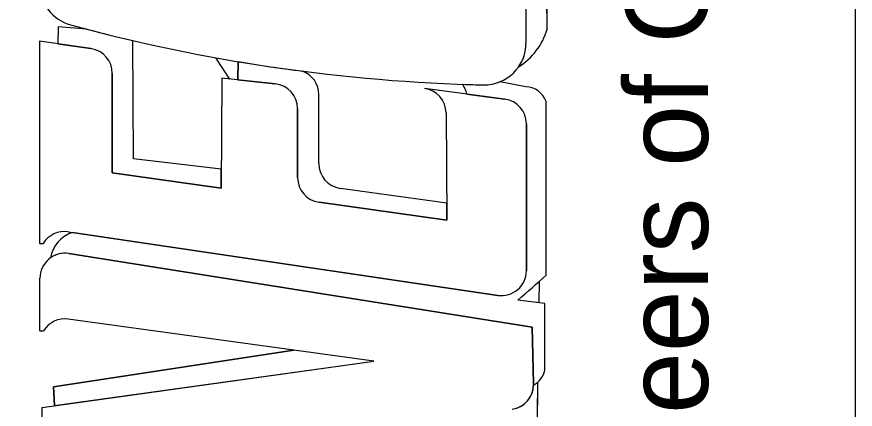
# Model space of a CAD drawing. Extents: x 1485751 to 1485785, y 230696.6 to 230718.6.
# Drawn here: x 1485783.769 to 1485784.533, y 230715.175 to 230715.532 of the extents above; entities that cross this region are included whole.
import ezdxf

# ---------------------------------------------------------------- set-up
doc = ezdxf.new("R2010")
doc.units = 0
doc.layers.add('SH_Border', color=7, linetype='Continuous')

msp = doc.modelspace()

# ---------------------------------------------------------------- linework, layer by layer
at = {"layer": 'SH_Border'}
for p, q in [((1485784.25235, 230715.52061), (1485784.25132, 230715.64075)), ((1485784.25235, 230715.52061), (1485784.25132, 230715.64075)), ((1485784.25235, 230715.52061), (1485784.25132, 230715.64075)), ((1485784.23301, 230715.61233), (1485784.23301, 230715.5077)), ((1485784.23301, 230715.61233), (1485784.23301, 230715.5077)), ((1485784.23301, 230715.61233), (1485784.23301, 230715.5077)), ((1485783.80699, 230715.52266), (1485783.80683, 230715.50714)), ((1485783.80699, 230715.52266), (1485783.80683, 230715.50714)), ((1485783.80699, 230715.52266), (1485783.80683, 230715.50714)), ((1485783.83291, 230715.52058), (1485783.80699, 230715.52266)), ((1485783.83291, 230715.52058), (1485783.80699, 230715.52266)), ((1485783.83291, 230715.52058), (1485783.80699, 230715.52266)), ((1485783.83689, 230715.50284), (1485783.79009, 230715.50953)), ((1485783.79009, 230715.50953), (1485783.79009, 230715.32551)), ((1485783.83689, 230715.50284), (1485783.79009, 230715.50953)), ((1485783.79009, 230715.50953), (1485783.79009, 230715.32551)), ((1485783.83689, 230715.50284), (1485783.79009, 230715.50953)), ((1485783.79009, 230715.50953), (1485783.79009, 230715.32551)), ((1485783.87574, 230715.40252), (1485783.87515, 230715.51016)), ((1485783.87574, 230715.40252), (1485783.87515, 230715.51016)), ((1485783.87574, 230715.40252), (1485783.87515, 230715.51016)), ((1485783.96336, 230715.47519), (1485783.95069, 230715.49456)), ((1485783.96336, 230715.47519), (1485783.95069, 230715.49456)), ((1485783.96336, 230715.47519), (1485783.95069, 230715.49456)), ((1485783.97073, 230715.47442), (1485783.97099, 230715.49103)), ((1485783.97073, 230715.47442), (1485783.97099, 230715.49103)), ((1485783.97073, 230715.47442), (1485783.97099, 230715.49103)), ((1485783.85637, 230715.38981), (1485783.85637, 230715.48038)), ((1485783.85637, 230715.38981), (1485783.85637, 230715.48038)), ((1485783.85637, 230715.38981), (1485783.85637, 230715.48038)), ((1485783.95622, 230715.47594), (1485783.95536, 230715.37602)), ((1485783.95622, 230715.47594), (1485783.95536, 230715.37602)), ((1485783.95622, 230715.47594), (1485783.95536, 230715.37602)), ((1485784.00475, 230715.47087), (1485783.95622, 230715.47594)), ((1485784.00475, 230715.47087), (1485783.95622, 230715.47594)), ((1485784.00475, 230715.47087), (1485783.95622, 230715.47594)), ((1485784.23285, 230715.46824), (1485784.20934, 230715.47262)), ((1485784.23285, 230715.46824), (1485784.20934, 230715.47262)), ((1485784.23285, 230715.46824), (1485784.20934, 230715.47262)), ((1485784.2137, 230715.45692), (1485784.14059, 230715.46667)), ((1485784.2137, 230715.45692), (1485784.14059, 230715.46667)), ((1485784.2137, 230715.45692), (1485784.14059, 230715.46667)), ((1485784.04446, 230715.39822), (1485784.04446, 230715.46102)), ((1485784.04446, 230715.39822), (1485784.04446, 230715.46102)), ((1485784.04446, 230715.39822), (1485784.04446, 230715.46102)), ((1485784.25132, 230715.29676), (1485784.25132, 230715.45489)), ((1485784.25132, 230715.29676), (1485784.25132, 230715.45489)), ((1485784.25132, 230715.29676), (1485784.25132, 230715.45489)), ((1485784.02508, 230715.38551), (1485784.02508, 230715.4483)), ((1485784.02508, 230715.38551), (1485784.02508, 230715.4483)), ((1485784.02508, 230715.38551), (1485784.02508, 230715.4483)), ((1485784.16028, 230715.44437), (1485784.16109, 230715.34674)), ((1485784.16028, 230715.44437), (1485784.16109, 230715.34674)), ((1485784.16028, 230715.44437), (1485784.16109, 230715.34674)), ((1485784.23339, 230715.30084), (1485784.23339, 230715.43443)), ((1485784.23339, 230715.30084), (1485784.23339, 230715.43443)), ((1485784.23339, 230715.30084), (1485784.23339, 230715.43443)), ((1485783.95551, 230715.39327), (1485783.87574, 230715.40252)), ((1485783.95551, 230715.39327), (1485783.87574, 230715.40252)), ((1485783.95551, 230715.39327), (1485783.87574, 230715.40252)), ((1485783.95536, 230715.37602), (1485783.85637, 230715.38981)), ((1485783.95536, 230715.37602), (1485783.85637, 230715.38981)), ((1485783.95536, 230715.37602), (1485783.85637, 230715.38981)), ((1485784.16096, 230715.36218), (1485784.064, 230715.37575)), ((1485784.16096, 230715.36218), (1485784.064, 230715.37575)), ((1485784.16096, 230715.36218), (1485784.064, 230715.37575)), ((1485784.16109, 230715.34674), (1485784.04463, 230715.36304)), ((1485784.16109, 230715.34674), (1485784.04463, 230715.36304)), ((1485784.16109, 230715.34674), (1485784.04463, 230715.36304)), ((1485783.81609, 230715.33622), (1485784.20739, 230715.2784)), ((1485783.81609, 230715.33622), (1485784.20739, 230715.2784)), ((1485783.81609, 230715.33622), (1485784.20739, 230715.2784)), ((1485783.79009, 230715.32551), (1485783.79336, 230715.32551)), ((1485783.79009, 230715.32551), (1485783.79336, 230715.32551)), ((1485783.79009, 230715.32551), (1485783.79336, 230715.32551)), ((1485784.23859, 230715.24939), (1485783.81676, 230715.31644)), ((1485784.23859, 230715.24939), (1485783.81676, 230715.31644)), ((1485784.23859, 230715.24939), (1485783.81676, 230715.31644)), ((1485783.79051, 230715.2461), (1485783.79051, 230715.29404)), ((1485783.79051, 230715.2461), (1485783.79051, 230715.29404)), ((1485783.79051, 230715.2461), (1485783.79051, 230715.29404)), ((1485784.2451, 230715.27174), (1485784.24545, 230715.29141)), ((1485784.2451, 230715.27174), (1485784.24545, 230715.29141)), ((1485784.2451, 230715.27174), (1485784.24545, 230715.29141)), ((1485784.2503, 230715.27109), (1485784.22567, 230715.27417)), ((1485784.2503, 230715.27109), (1485784.22567, 230715.27417)), ((1485784.2503, 230715.27109), (1485784.22567, 230715.27417)), ((1485784.2503, 230715.2105), (1485784.2503, 230715.27109)), ((1485784.2503, 230715.2105), (1485784.2503, 230715.27109)), ((1485784.2503, 230715.2105), (1485784.2503, 230715.27109)), ((1485784.09452, 230715.21839), (1485783.8163, 230715.25684)), ((1485784.09452, 230715.21839), (1485783.8163, 230715.25684)), ((1485784.09452, 230715.21839), (1485783.8163, 230715.25684)), ((1485783.79051, 230715.2461), (1485783.79378, 230715.2461)), ((1485783.79051, 230715.2461), (1485783.79378, 230715.2461)), ((1485783.79051, 230715.2461), (1485783.79378, 230715.2461)), ((1485784.23995, 230715.19789), (1485784.23859, 230715.24939)), ((1485784.23995, 230715.19789), (1485784.23859, 230715.24939)), ((1485784.23995, 230715.19789), (1485784.23859, 230715.24939)), ((1485783.80289, 230715.1951), (1485784.02153, 230715.22848)), ((1485783.80289, 230715.1951), (1485784.02153, 230715.22848)), ((1485783.80289, 230715.1951), (1485784.02153, 230715.22848)), ((1485783.79244, 230715.17654), (1485784.09452, 230715.21839)), ((1485783.79244, 230715.17654), (1485784.09452, 230715.21839)), ((1485783.79244, 230715.17654), (1485784.09452, 230715.21839)), ((1485784.24304, 230715.11402), (1485784.24376, 230715.19938)), ((1485784.24304, 230715.11402), (1485784.24376, 230715.19938)), ((1485784.24304, 230715.11402), (1485784.24376, 230715.19938)), ((1485783.80385, 230715.17812), (1485783.80289, 230715.1951)), ((1485783.80385, 230715.17812), (1485783.80289, 230715.1951)), ((1485783.80385, 230715.17812), (1485783.80289, 230715.1951)), ((1485783.79244, 230715.11608), (1485783.79244, 230715.17654)), ((1485783.79244, 230715.11608), (1485783.79244, 230715.17654)), ((1485783.79244, 230715.11608), (1485783.79244, 230715.17654))]:
    msp.add_line(p, q, dxfattribs=at)
msp.add_lwpolyline([(1485753.03285, 230718.14083), (1485784.53285, 230718.14083), (1485784.53285, 230697.14083), (1485753.03285, 230697.14083)], close=True, dxfattribs=at)
for points in [[(1485784.25235, 230715.52061), (1485784.25132, 230715.64075)], [(1485784.25235, 230715.52061), (1485784.25132, 230715.64075)], [(1485784.25235, 230715.52061), (1485784.25132, 230715.64075)], [(1485784.23301, 230715.61233), (1485784.23301, 230715.5077)], [(1485784.23301, 230715.61233), (1485784.23301, 230715.5077)], [(1485784.23301, 230715.61233), (1485784.23301, 230715.5077)], [(1485783.83291, 230715.52058), (1485783.80699, 230715.52266), (1485783.80683, 230715.50714), (1485783.83689, 230715.50284)], [(1485783.83291, 230715.52058), (1485783.80699, 230715.52266), (1485783.80683, 230715.50714), (1485783.83689, 230715.50284)], [(1485783.83291, 230715.52058), (1485783.80699, 230715.52266), (1485783.80683, 230715.50714), (1485783.83689, 230715.50284)], [(1485783.85637, 230715.48038), (1485783.85637, 230715.38981), (1485783.95536, 230715.37602), (1485783.95551, 230715.39327), (1485783.87574, 230715.40252), (1485783.87515, 230715.51016)], [(1485783.85637, 230715.48038), (1485783.85637, 230715.38981), (1485783.95536, 230715.37602), (1485783.95551, 230715.39327), (1485783.87574, 230715.40252), (1485783.87515, 230715.51016)], [(1485783.85637, 230715.48038), (1485783.85637, 230715.38981), (1485783.95536, 230715.37602), (1485783.95551, 230715.39327), (1485783.87574, 230715.40252), (1485783.87515, 230715.51016)], [(1485783.97099, 230715.49103), (1485783.97073, 230715.47442), (1485784.00475, 230715.47087)], [(1485783.97099, 230715.49103), (1485783.97073, 230715.47442), (1485784.00475, 230715.47087)], [(1485783.97099, 230715.49103), (1485783.97073, 230715.47442), (1485784.00475, 230715.47087)], [(1485784.23285, 230715.46824), (1485784.20934, 230715.47262)], [(1485784.23285, 230715.46824), (1485784.20934, 230715.47262)], [(1485784.23285, 230715.46824), (1485784.20934, 230715.47262)], [(1485784.04446, 230715.39822), (1485784.04446, 230715.46102)], [(1485784.04446, 230715.39822), (1485784.04446, 230715.46102)], [(1485784.04446, 230715.39822), (1485784.04446, 230715.46102)], [(1485784.17918, 230715.46152), (1485784.2137, 230715.45692)], [(1485784.17918, 230715.46152), (1485784.2137, 230715.45692)], [(1485784.17918, 230715.46152), (1485784.2137, 230715.45692)], [(1485784.25132, 230715.29676), (1485784.25132, 230715.45489)], [(1485784.25132, 230715.29676), (1485784.25132, 230715.45489)], [(1485784.25132, 230715.29676), (1485784.25132, 230715.45489)], [(1485784.02508, 230715.4483), (1485784.02508, 230715.38551)], [(1485784.02508, 230715.4483), (1485784.02508, 230715.38551)], [(1485784.02508, 230715.4483), (1485784.02508, 230715.38551)], [(1485784.23339, 230715.43443), (1485784.23339, 230715.30084)], [(1485784.23339, 230715.43443), (1485784.23339, 230715.30084)], [(1485784.23339, 230715.43443), (1485784.23339, 230715.30084)], [(1485784.04463, 230715.36304), (1485784.16109, 230715.34674), (1485784.16096, 230715.36218), (1485784.064, 230715.37575)], [(1485784.04463, 230715.36304), (1485784.16109, 230715.34674), (1485784.16096, 230715.36218), (1485784.064, 230715.37575)], [(1485784.04463, 230715.36304), (1485784.16109, 230715.34674), (1485784.16096, 230715.36218), (1485784.064, 230715.37575)], [(1485784.20739, 230715.2784), (1485783.81978, 230715.33567)], [(1485784.20739, 230715.2784), (1485783.81978, 230715.33567)], [(1485784.20739, 230715.2784), (1485783.81978, 230715.33567)], [(1485783.81676, 230715.31644), (1485784.23859, 230715.24939), (1485784.23995, 230715.19789)], [(1485783.81676, 230715.31644), (1485784.23859, 230715.24939), (1485784.23995, 230715.19789)], [(1485783.81676, 230715.31644), (1485784.23859, 230715.24939), (1485784.23995, 230715.19789)], [(1485784.2503, 230715.2105), (1485784.2503, 230715.27109), (1485784.2451, 230715.27174), (1485784.22567, 230715.27417)], [(1485784.2503, 230715.2105), (1485784.2503, 230715.27109), (1485784.2451, 230715.27174), (1485784.22567, 230715.27417)], [(1485784.2503, 230715.2105), (1485784.2503, 230715.27109), (1485784.2451, 230715.27174), (1485784.22567, 230715.27417)], [(1485783.80385, 230715.17812), (1485784.09452, 230715.21839), (1485784.02153, 230715.22848), (1485783.80289, 230715.1951), (1485783.80385, 230715.17812)], [(1485783.80385, 230715.17812), (1485784.09452, 230715.21839), (1485784.02153, 230715.22848), (1485783.80289, 230715.1951), (1485783.80385, 230715.17812)], [(1485783.80385, 230715.17812), (1485784.09452, 230715.21839), (1485784.02153, 230715.22848), (1485783.80289, 230715.1951), (1485783.80385, 230715.17812)], [(1485784.15842, 230715.16607), (1485784.18677, 230715.12362), (1485784.24304, 230715.11402), (1485784.24376, 230715.19938)], [(1485784.15842, 230715.16607), (1485784.18677, 230715.12362), (1485784.24304, 230715.11402), (1485784.24376, 230715.19938)], [(1485784.15842, 230715.16607), (1485784.18677, 230715.12362), (1485784.24304, 230715.11402), (1485784.24376, 230715.19938)]]:
    msp.add_lwpolyline(points, dxfattribs=at)
for centre, radius, start, end in [((1485783.82829, 230715.56095), 0.03781, 180, 254.79162), ((1485783.82829, 230715.56095), 0.03781, 180, 254.79162), ((1485783.82829, 230715.56095), 0.03781, 180, 254.79162), ((1485784.23016, 230717.0392), 1.56971, 254.79162, 268.69253), ((1485784.23016, 230717.0392), 1.56971, 254.79162, 268.69253), ((1485784.23016, 230717.0392), 1.56971, 254.79162, 268.69253), ((1485784.23016, 230717.0392), 1.56971, 255.34062, 256.92894), ((1485784.23016, 230717.0392), 1.56971, 255.34062, 256.92894), ((1485784.23016, 230717.0392), 1.56971, 255.34062, 256.92894), ((1485784.19322, 230715.53826), 0.06171, 302.39655, 343.37547), ((1485784.19322, 230715.53826), 0.06171, 302.39655, 343.37547), ((1485784.19322, 230715.53826), 0.06171, 302.39655, 343.37547), ((1485784.19322, 230715.53826), 0.06171, 302.39655, 343.37547), ((1485784.19322, 230715.53826), 0.06171, 302.39655, 343.37547), ((1485784.19322, 230715.53826), 0.06171, 302.39655, 343.37547), ((1485784.1952, 230715.5077), 0.03781, 268.69253, 0), ((1485784.1952, 230715.5077), 0.03781, 268.69253, 0), ((1485784.1952, 230715.5077), 0.03781, 268.69253, 0), ((1485784.1952, 230715.5077), 0.03781, 325.27661, 0), ((1485784.1952, 230715.5077), 0.03781, 325.27661, 0), ((1485784.1952, 230715.5077), 0.03781, 325.27661, 0), ((1485783.83368, 230715.48038), 0.02269, 0, 81.86464), ((1485783.83368, 230715.48038), 0.02269, 0, 81.86464), ((1485783.83368, 230715.48038), 0.02269, 0, 81.86464), ((1485783.83368, 230715.48038), 0.02269, 0, 81.86464), ((1485783.83368, 230715.48038), 0.02269, 0, 81.86464), ((1485783.83368, 230715.48038), 0.02269, 0, 81.86464), ((1485784.23016, 230717.0392), 1.56971, 260.49664, 262.65334), ((1485784.23016, 230717.0392), 1.56971, 260.49664, 262.65334), ((1485784.23016, 230717.0392), 1.56971, 260.49664, 262.65334), ((1485784.02177, 230715.46102), 0.02269, 0, 70.25544), ((1485784.02177, 230715.46102), 0.02269, 0, 70.25544), ((1485784.02177, 230715.46102), 0.02269, 0, 70.25544), ((1485784.02177, 230715.46102), 0.02269, 0, 70.25544), ((1485784.02177, 230715.46102), 0.02269, 0, 70.25544), ((1485784.02177, 230715.46102), 0.02269, 0, 70.25544), ((1485784.1952, 230715.5077), 0.03781, 268.69253, 291.95024), ((1485784.1952, 230715.5077), 0.03781, 268.69253, 291.95024), ((1485784.1952, 230715.5077), 0.03781, 268.69253, 291.95024), ((1485784.00239, 230715.4483), 0.02269, 0, 84.03166), ((1485784.00239, 230715.4483), 0.02269, 0, 84.03166), ((1485784.00239, 230715.4483), 0.02269, 0, 84.03166), ((1485784.00239, 230715.4483), 0.02269, 0, 84.03166), ((1485784.00239, 230715.4483), 0.02269, 0, 84.03166), ((1485784.00239, 230715.4483), 0.02269, 0, 84.03166), ((1485784.13759, 230715.44418), 0.02269, 0.4732, 82.40046), ((1485784.13759, 230715.44418), 0.02269, 0.4732, 82.40046), ((1485784.13759, 230715.44418), 0.02269, 0.4732, 82.40046), ((1485784.15697, 230715.4569), 0.02269, 11.76029, 36.6658), ((1485784.23016, 230717.0392), 1.56971, 267.99237, 268.69253), ((1485784.15697, 230715.4569), 0.02269, 11.76029, 36.6658), ((1485784.15697, 230715.4569), 0.02269, 11.76029, 36.6658), ((1485784.23016, 230717.0392), 1.56971, 267.99237, 268.69253), ((1485784.15697, 230715.4569), 0.02269, 11.76029, 36.6658), ((1485784.15697, 230715.4569), 0.02269, 11.76029, 36.6658), ((1485784.23016, 230717.0392), 1.56971, 267.99237, 268.69253), ((1485784.15697, 230715.4569), 0.02269, 11.76029, 36.6658), ((1485784.23207, 230715.44771), 0.02055, 20.45964, 87.82957), ((1485784.23207, 230715.44771), 0.02055, 20.45964, 87.82957), ((1485784.23207, 230715.44771), 0.02055, 20.45964, 87.82957), ((1485784.23207, 230715.44771), 0.02055, 20.45964, 87.82957), ((1485784.23207, 230715.44771), 0.02055, 20.45964, 87.82957), ((1485784.23207, 230715.44771), 0.02055, 20.45964, 87.82957), ((1485784.2107, 230715.43443), 0.02269, 0, 82.40046), ((1485784.2107, 230715.43443), 0.02269, 0, 82.40046), ((1485784.2107, 230715.43443), 0.02269, 0, 82.40046), ((1485784.2107, 230715.43443), 0.02269, 0, 82.40046), ((1485784.2107, 230715.43443), 0.02269, 0, 82.40046), ((1485784.2107, 230715.43443), 0.02269, 0, 82.40046), ((1485784.06714, 230715.39822), 0.02269, 180, 262.03311), ((1485784.06714, 230715.39822), 0.02269, 180, 262.03311), ((1485784.06714, 230715.39822), 0.02269, 180, 262.03311), ((1485784.06714, 230715.39822), 0.02269, 180, 262.03311), ((1485784.06714, 230715.39822), 0.02269, 180, 262.03311), ((1485784.06714, 230715.39822), 0.02269, 180, 262.03311), ((1485784.04777, 230715.38551), 0.02269, 180, 262.03311), ((1485784.04777, 230715.38551), 0.02269, 180, 262.03311), ((1485784.04777, 230715.38551), 0.02269, 180, 262.03311), ((1485784.04777, 230715.38551), 0.02269, 180, 262.03311), ((1485784.04777, 230715.38551), 0.02269, 180, 262.03311), ((1485784.04777, 230715.38551), 0.02269, 180, 262.03311), ((1485783.81278, 230715.31378), 0.02269, 81.59392, 148.85913), ((1485783.81278, 230715.31378), 0.02269, 81.59392, 148.85913), ((1485783.81278, 230715.31378), 0.02269, 81.59392, 148.85913), ((1485783.82978, 230715.30715), 0.03022, 109.32309, 169.78308), ((1485783.82978, 230715.30715), 0.03022, 109.32309, 169.78308), ((1485783.82978, 230715.30715), 0.03022, 109.32309, 169.78308), ((1485783.82978, 230715.30715), 0.03022, 109.32309, 169.78308), ((1485783.82978, 230715.30715), 0.03022, 109.32309, 169.78308), ((1485783.82978, 230715.30715), 0.03022, 109.32309, 169.78308), ((1485783.8132, 230715.29404), 0.02269, 80.96848, 180), ((1485783.8132, 230715.29404), 0.02269, 80.96848, 180), ((1485783.8132, 230715.29404), 0.02269, 80.96848, 180), ((1485783.8132, 230715.29404), 0.02269, 80.96848, 125.47349), ((1485783.8132, 230715.29404), 0.02269, 80.96848, 125.47349), ((1485783.8132, 230715.29404), 0.02269, 80.96848, 125.47349), ((1485784.2107, 230715.30084), 0.02269, 261.59392, 0), ((1485784.2107, 230715.30084), 0.02269, 261.59392, 0), ((1485784.2107, 230715.30084), 0.02269, 261.59392, 0), ((1485784.2107, 230715.30084), 0.02269, 261.59392, 0), ((1485784.2107, 230715.30084), 0.02269, 261.59392, 0), ((1485784.2107, 230715.30084), 0.02269, 261.59392, 0), ((1485783.73286, 230715.85967), 0.7653, 310.08662, 312.64602), ((1485783.73286, 230715.85967), 0.7653, 310.08662, 312.64602), ((1485783.73286, 230715.85967), 0.7653, 310.08662, 312.64602), ((1485783.73286, 230715.85967), 0.7653, 310.08662, 312.64602), ((1485783.73286, 230715.85967), 0.7653, 310.08662, 312.64602), ((1485783.73286, 230715.85967), 0.7653, 310.08662, 312.64602), ((1485783.8132, 230715.23437), 0.02269, 82.13091, 148.85913), ((1485783.8132, 230715.23437), 0.02269, 82.13091, 148.85913), ((1485783.8132, 230715.23437), 0.02269, 82.13091, 148.85913), ((1485784.2297, 230715.21513), 0.02111, 299.03105, 347.33987), ((1485784.2297, 230715.21513), 0.02111, 299.03105, 347.33987), ((1485784.2297, 230715.21513), 0.02111, 299.03105, 347.33987), ((1485784.2297, 230715.21513), 0.02111, 299.03105, 347.33987), ((1485784.2297, 230715.21513), 0.02111, 299.03105, 347.33987), ((1485784.2297, 230715.21513), 0.02111, 299.03105, 347.33987), ((1485784.21727, 230715.19729), 0.02269, 278.04089, 1.50643), ((1485784.21727, 230715.19729), 0.02269, 278.04089, 1.50643), ((1485784.21727, 230715.19729), 0.02269, 278.04089, 1.50643), ((1485784.21727, 230715.19729), 0.02269, 358.43264, 1.50643), ((1485784.21727, 230715.19729), 0.02269, 358.43264, 1.50643), ((1485784.21727, 230715.19729), 0.02269, 358.43264, 1.50643), ((1485784.21727, 230715.19729), 0.02269, 278.04089, 358.43264), ((1485784.21727, 230715.19729), 0.02269, 278.04089, 358.43264), ((1485784.21727, 230715.19729), 0.02269, 278.04089, 358.43264)]:
    msp.add_arc(centre, radius, start, end, dxfattribs=at)

# ---------------------------------------------------------------- texts
msp.add_text('Engineers of Ohio, Inc.', height=0.075625, rotation=90, dxfattribs=at).set_placement((1485784.39868, 230714.91187))

doc.saveas('drawing.dxf')
